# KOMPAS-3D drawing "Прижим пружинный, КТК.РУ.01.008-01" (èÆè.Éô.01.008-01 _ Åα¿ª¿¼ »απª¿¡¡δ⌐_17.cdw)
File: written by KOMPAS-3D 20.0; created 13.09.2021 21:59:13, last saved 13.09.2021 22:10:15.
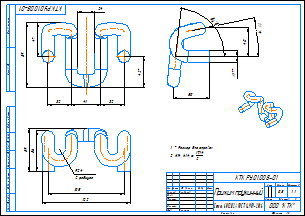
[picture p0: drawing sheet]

Sheet 1: A3, landscape

Document properties: Масса: 0.795288

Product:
- Part/product: Прижим пружинный  | designation КТК.РУ.01.008-01
    Материал: Сталь 60С2Н2А ГОСТ 14959-2016 (density 7680 kg/m3)
    Масса: 0.795288
    source file: КТК.РУ.01.008-01 _ Прижим пружинный_17.cdw, прижим пружинный на отправку\КТК.РУ.01.008 _ Прижим пружинный.cdw

Title block, sheet 1: Наименование: Прижим пружинный; designation: КТК.РУ.01.008-01; Материал: Сталь 60С2Н2А ГОСТ 14959-2016; Масса: 0,8; Количество листов документа: 1; organisation: ООО "КТК"; Форматы листов документа: A3; stored path: E:\Мои документы\КТК\Роликовое устройство\Разработанное\РУ перевернутые болты\КТК.РУ.01.008-01 _ Прижим пружинный_17.cdw; Разработал: Кордюков; Утвердил: Кузьмин

Views: Вид 1, Спереди, Проекционный вид 2, Проекционный вид 3, Вид 5, Изометрия
Referenced files in E:\Мои документы\КТК\Роликовое устройство\Разработанное\РУ перевернутые болты\прижим пружинный на отправку\: КТК.РУ.01.008 _ Прижим пружинный_17.m3d
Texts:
  Symbol type A
  КТК.РУ.01.008-01 Прижим пружинный
Dimensions and other numbers on the sheet: 89; 47; 41; 32; 42; 24; 105; 122; 59; 2 радиуса; 56; 84 8'; 40; 50; 17; 11; 4; 1:1; 1; 0,8

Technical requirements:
  * Размер для справок.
